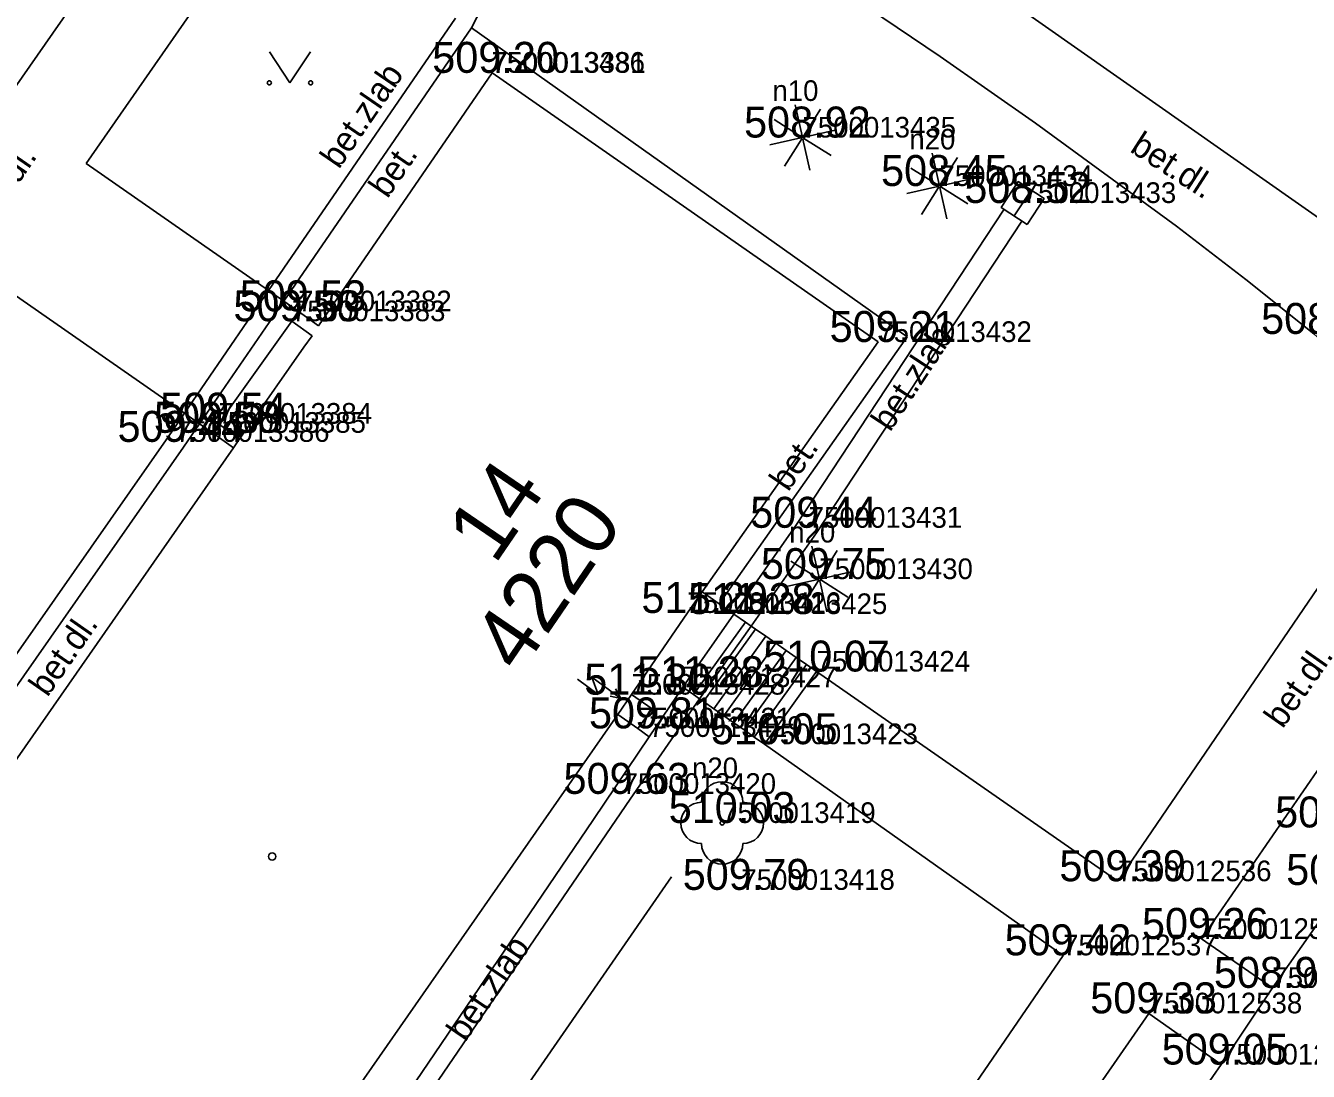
# Model space of a CAD drawing. Extents: x -669251 to -668549, y -1128351 to -1127698.
# Drawn here: x -668889.3 to -668858.22, y -1127834.53 to -1127809.2 of the extents above; entities that cross this region are included whole.
import ezdxf

# ---------------------------------------------------------------- set-up
doc = ezdxf.new("R2010")
doc.units = 0
for name, color, linetype in [('Vrstva 1', 7, 'Continuous'), ('Vrstva 10', 7, 'Continuous'), ('Vrstva 11', 7, 'Continuous'), ('Vrstva 14', 7, 'Continuous'), ('Vrstva 2', 7, 'Continuous'), ('Vrstva 22', 7, 'Continuous'), ('Vrstva 24', 7, 'Continuous'), ('Vrstva 27', 7, 'Continuous'), ('Vrstva 3', 7, 'Continuous'), ('Vrstva 36', 7, 'Continuous'), ('Vrstva 40', 7, 'Continuous'), ('Vrstva 43', 7, 'Continuous'), ('Vrstva 44', 7, 'Continuous'), ('Vrstva 47', 7, 'Continuous'), ('Vrstva 5', 7, 'Continuous'), ('Vrstva 58', 7, 'Continuous'), ('Vrstva 6', 7, 'Continuous')]:
    doc.layers.add(name, color=color, linetype=linetype)

msp = doc.modelspace()

# ---------------------------------------------------------------- linework, layer by layer
at = {"layer": 'Vrstva 1'}
for p, q in [((-668878.013, -1127810.343), (-668878.013, -1127810.343)), ((-668877.996, -1127810.346), (-668877.996, -1127810.346)), ((-668870.478, -1127811.913), (-668870.478, -1127811.913)), ((-668867.161, -1127813.087), (-668867.161, -1127813.087)), ((-668865.144, -1127813.498), (-668865.144, -1127813.498)), ((-668882.696, -1127816.122), (-668882.696, -1127816.122)), ((-668882.848, -1127816.362), (-668882.848, -1127816.362)), ((-668868.642, -1127816.865), (-668868.642, -1127816.865)), ((-668884.627, -1127818.844), (-668884.627, -1127818.844)), ((-668885.656, -1127819.284), (-668885.656, -1127819.284)), ((-668884.775, -1127819.064), (-668884.775, -1127819.064)), ((-668870.329, -1127821.365), (-668870.329, -1127821.365)), ((-668870.07, -1127822.608), (-668870.07, -1127822.608)), ((-668873.267, -1127823.428), (-668873.267, -1127823.428)), ((-668872.143, -1127823.455), (-668872.143, -1127823.455)), ((-668870.137, -1127824.847), (-668870.137, -1127824.847)), ((-668874.62, -1127825.406), (-668874.62, -1127825.406)), ((-668873.376, -1127825.226), (-668873.376, -1127825.226)), ((-668874.472, -1127826.224), (-668874.472, -1127826.224)), ((-668874.193, -1127826.431), (-668874.193, -1127826.431)), ((-668871.401, -1127826.607), (-668871.401, -1127826.607)), ((-668874.838, -1127827.81), (-668874.838, -1127827.81)), ((-668872.425, -1127828.515), (-668872.425, -1127828.515)), ((-668871.96, -1127830.135), (-668871.96, -1127830.135)), ((-668862.836, -1127829.926), (-668862.836, -1127829.926)), ((-668860.815, -1127831.323), (-668860.815, -1127831.323)), ((-668864.165, -1127831.721), (-668864.165, -1127831.721)), ((-668859.096, -1127832.509), (-668859.096, -1127832.509)), ((-668862.091, -1127833.126), (-668862.091, -1127833.126)), ((-668860.339, -1127834.366), (-668860.339, -1127834.366))]:
    msp.add_line(p, q, dxfattribs=at)
at = {"layer": 'Vrstva 10'}
for p, q in [((-668907.589, -1127779.058), (-668856.591, -1127814.83)), ((-668879.97, -1127801.247), (-668887.836, -1127812.543)), ((-668900.288, -1127826.082), (-668886.406, -1127806.172)), ((-668876.868, -1127806.118), (-668878.5, -1127809.256)), ((-668878.886, -1127809.024), (-668883.415, -1127815.621)), ((-668878.5, -1127809.256), (-668883.045, -1127815.878)), ((-668878.5, -1127809.256), (-668867.944, -1127816.742)), ((-668883.415, -1127815.621), (-668887.836, -1127812.543)), ((-668865.594, -1127813.65), (-668870.64, -1127821.307)), ((-668865.162, -1127813.935), (-668870.143, -1127821.491)), ((-668885.454, -1127818.591), (-668889.894, -1127815.499)), ((-668883.415, -1127815.621), (-668885.454, -1127818.591)), ((-668883.045, -1127815.878), (-668883.415, -1127815.621)), ((-668883.045, -1127815.878), (-668885.084, -1127818.848)), ((-668882.696, -1127816.122), (-668883.045, -1127815.878)), ((-668867.944, -1127816.742), (-668872.498, -1127823.205)), ((-668885.454, -1127818.591), (-668885.841, -1127819.156)), ((-668885.084, -1127818.848), (-668885.454, -1127818.591)), ((-668885.084, -1127818.848), (-668885.471, -1127819.412)), ((-668884.775, -1127819.064), (-668885.084, -1127818.848)), ((-668893.205, -1127829.685), (-668885.841, -1127819.156)), ((-668855.496, -1127819.148), (-668862.836, -1127829.926)), ((-668892.835, -1127829.943), (-668885.471, -1127819.412)), ((-668870.64, -1127821.307), (-668872.143, -1127823.455)), ((-668870.143, -1127821.491), (-668871.721, -1127823.748)), ((-668860.815, -1127831.323), (-668854.159, -1127821.653)), ((-668871.721, -1127823.748), (-668872.974, -1127825.506)), ((-668862.836, -1127829.926), (-668870.137, -1127824.847)), ((-668872.974, -1127825.506), (-668874.654, -1127827.939)), ((-668874.193, -1127826.431), (-668875.54, -1127828.434)), ((-668871.401, -1127826.607), (-668864.165, -1127831.721)), ((-668874.654, -1127827.939), (-668881.914, -1127838.571)), ((-668875.54, -1127828.434), (-668882.273, -1127838.332)), ((-668859.096, -1127832.509), (-668857.344, -1127830.016)), ((-668860.815, -1127831.323), (-668859.096, -1127832.509)), ((-668872.983, -1127844.597), (-668864.165, -1127831.721)), ((-668860.339, -1127834.366), (-668859.096, -1127832.509)), ((-668871.001, -1127845.97), (-668862.091, -1127833.126)), ((-668862.091, -1127833.126), (-668860.339, -1127834.366)), ((-668869.228, -1127847.16), (-668860.339, -1127834.366))]:
    msp.add_line(p, q, dxfattribs=at)
msp.add_lwpolyline([(-668879.97, -1127801.247), (-668874.443, -1127805.031), (-668870.265, -1127807.831), (-668867.147, -1127809.949), (-668864.831, -1127811.565), (-668861.415, -1127814.059), (-668859.741, -1127815.348), (-668858.095, -1127816.67), (-668857.422, -1127817.261), (-668856.456, -1127818.201), (-668855.496, -1127819.148)], dxfattribs=at)
at = {"layer": 'Vrstva 11'}
for p, q in [((-668872.907, -1127822.917), (-668872.498, -1127823.205)), ((-668872.498, -1127823.205), (-668872.143, -1127823.455)), ((-668872.143, -1127823.455), (-668873.376, -1127825.226)), ((-668872.143, -1127823.455), (-668871.863, -1127823.65)), ((-668871.863, -1127823.65), (-668873.122, -1127825.403)), ((-668871.616, -1127823.821), (-668872.876, -1127825.575)), ((-668871.616, -1127823.821), (-668871.37, -1127823.992)), ((-668871.37, -1127823.992), (-668872.63, -1127825.747)), ((-668871.123, -1127824.163), (-668872.385, -1127825.919)), ((-668871.37, -1127823.992), (-668871.123, -1127824.163)), ((-668871.123, -1127824.163), (-668870.877, -1127824.334)), ((-668870.877, -1127824.334), (-668872.139, -1127826.091)), ((-668870.63, -1127824.505), (-668871.893, -1127826.263)), ((-668870.877, -1127824.334), (-668870.63, -1127824.505)), ((-668870.63, -1127824.505), (-668870.384, -1127824.676)), ((-668870.384, -1127824.676), (-668871.647, -1127826.435)), ((-668870.137, -1127824.847), (-668871.401, -1127826.607)), ((-668870.384, -1127824.676), (-668870.137, -1127824.847)), ((-668873.376, -1127825.226), (-668874.193, -1127826.431)), ((-668873.376, -1127825.226), (-668873.122, -1127825.403)), ((-668873.122, -1127825.403), (-668872.974, -1127825.506)), ((-668872.974, -1127825.506), (-668872.876, -1127825.575)), ((-668872.876, -1127825.575), (-668872.63, -1127825.747)), ((-668872.63, -1127825.747), (-668872.385, -1127825.919)), ((-668874.955, -1127825.887), (-668874.472, -1127826.224)), ((-668872.385, -1127825.919), (-668872.139, -1127826.091)), ((-668872.139, -1127826.091), (-668871.893, -1127826.263)), ((-668874.193, -1127826.431), (-668874.472, -1127826.224)), ((-668871.893, -1127826.263), (-668871.647, -1127826.435)), ((-668871.647, -1127826.435), (-668871.401, -1127826.607))]:
    msp.add_line(p, q, dxfattribs=at)
msp.add_lwpolyline([(-668871.863, -1127823.65), (-668871.721, -1127823.748), (-668871.616, -1127823.821)], dxfattribs=at)
at = {"layer": 'Vrstva 14'}
msp.add_line((-668880.4, -1127839.579), (-668873.655, -1127829.816), dxfattribs=at)
at = {"layer": 'Vrstva 22'}
for p, q in [((-668870.486, -1127811.873), (-668870.658, -1127811.119)), ((-668870.512, -1127811.893), (-668871.168, -1127811.479)), ((-668870.044, -1127811.223), (-668870.458, -1127811.879)), ((-668870.438, -1127811.905), (-668869.684, -1127811.733)), ((-668871.272, -1127812.093), (-668870.518, -1127811.921)), ((-668870.498, -1127811.947), (-668870.912, -1127812.603)), ((-668870.47, -1127811.953), (-668870.298, -1127812.707)), ((-668869.788, -1127812.347), (-668870.444, -1127811.933)), ((-668867.169, -1127813.047), (-668867.341, -1127812.293)), ((-668866.727, -1127812.397), (-668867.141, -1127813.053)), ((-668867.195, -1127813.067), (-668867.851, -1127812.653)), ((-668867.121, -1127813.079), (-668866.367, -1127812.907)), ((-668867.955, -1127813.267), (-668867.201, -1127813.095)), ((-668867.181, -1127813.121), (-668867.595, -1127813.777)), ((-668867.153, -1127813.127), (-668866.981, -1127813.881)), ((-668866.471, -1127813.521), (-668867.127, -1127813.107)), ((-668870.078, -1127822.568), (-668870.25, -1127821.814)), ((-668869.636, -1127821.918), (-668870.05, -1127822.574)), ((-668870.104, -1127822.588), (-668870.76, -1127822.174)), ((-668870.864, -1127822.788), (-668870.11, -1127822.616)), ((-668870.09, -1127822.642), (-668870.504, -1127823.298)), ((-668870.062, -1127822.648), (-668869.89, -1127823.402)), ((-668869.38, -1127823.042), (-668870.036, -1127822.628)), ((-668870.03, -1127822.6), (-668869.276, -1127822.428))]:
    msp.add_line(p, q, dxfattribs=at)
for centre, radius in [((-668870.478, -1127811.913), 0.04), ((-668867.161, -1127813.087), 0.04), ((-668870.07, -1127822.608), 0.04), ((-668872.425, -1127828.515), 0.05)]:
    msp.add_circle(centre, radius, dxfattribs=at)
for centre, start, end in [((-668872.425, -1127828.015), 0, 180), ((-668872.925, -1127828.515), 90, 270), ((-668871.925, -1127828.515), 270, 90), ((-668872.425, -1127829.015), 180, 0)]:
    msp.add_arc(centre, 0.5, start, end, dxfattribs=at)
at = {"layer": 'Vrstva 24'}
for p, q in [((-668875.933, -1127825.032), (-668875.43, -1127825.405)), ((-668875.43, -1127825.405), (-668875.582, -1127824.981)), ((-668875.582, -1127824.981), (-668874.88, -1127825.502)), ((-668875.142, -1127825.445), (-668874.88, -1127825.502)), ((-668874.88, -1127825.502), (-668875.011, -1127825.268)), ((-668874.62, -1127825.406), (-668874.123, -1127825.754)), ((-668874.122, -1127825.753), (-668874.472, -1127826.224))]:
    msp.add_line(p, q, dxfattribs=at)
at = {"layer": 'Vrstva 27'}
msp.add_line((-668865.35, -1127813.811), (-668864.938, -1127813.185), dxfattribs=at)
msp.add_lwpolyline([(-668865.038, -1127814.017), (-668864.625, -1127813.391), (-668865.252, -1127812.978), (-668865.664, -1127813.604)], close=True, dxfattribs=at)
at = {"layer": 'Vrstva 36'}
for p, q in [((-668883.395, -1127809.838), (-668882.895, -1127810.588)), ((-668882.895, -1127810.588), (-668882.395, -1127809.838))]:
    msp.add_line(p, q, dxfattribs=at)
for centre in [(-668883.396, -1127810.588), (-668882.396, -1127810.588)]:
    msp.add_circle(centre, 0.05, dxfattribs=at)
at = {"layer": 'Vrstva 5'}
for p, q in [((-668882.208, -1127816.472), (-668877.996, -1127810.346)), ((-668877.996, -1127810.346), (-668868.642, -1127816.865)), ((-668882.696, -1127816.122), (-668882.848, -1127816.362)), ((-668882.208, -1127816.472), (-668882.696, -1127816.122)), ((-668882.848, -1127816.362), (-668884.627, -1127818.844)), ((-668882.36, -1127816.712), (-668882.848, -1127816.362)), ((-668882.36, -1127816.712), (-668882.556, -1127816.99)), ((-668868.642, -1127816.865), (-668872.907, -1127822.917)), ((-668884.627, -1127818.844), (-668884.775, -1127819.064)), ((-668884.115, -1127819.211), (-668884.627, -1127818.844)), ((-668884.115, -1127819.211), (-668883.925, -1127818.941)), ((-668884.266, -1127819.429), (-668884.775, -1127819.064)), ((-668884.266, -1127819.429), (-668884.115, -1127819.211)), ((-668892.499, -1127831.244), (-668884.266, -1127819.429)), ((-668872.907, -1127822.917), (-668873.267, -1127823.428)), ((-668874.955, -1127825.887), (-668874.62, -1127825.406)), ((-668883.188, -1127837.699), (-668874.955, -1127825.887))]:
    msp.add_line(p, q, dxfattribs=at)
at = {"layer": 'Vrstva 58'}
msp.add_circle((-668883.326, -1127829.326), 0.0875, dxfattribs=at)
at = {"layer": 'Vrstva 6'}
for p, q in [((-668882.556, -1127816.99), (-668883.925, -1127818.941)), ((-668874.62, -1127825.406), (-668873.267, -1127823.428))]:
    msp.add_line(p, q, dxfattribs=at)

# ---------------------------------------------------------------- texts
at = {"layer": 'Vrstva 2'}
for s, p in [('7500013436', (-668878.013, -1127810.343)), ('7500013381', (-668877.996, -1127810.346)), ('7500013435', (-668870.478, -1127811.913)), ('7500013434', (-668867.161, -1127813.087)), ('7500013433', (-668865.144, -1127813.498)), ('7500013383', (-668882.848, -1127816.362)), ('7500013382', (-668882.696, -1127816.122)), ('7500013432', (-668868.642, -1127816.865)), ('7500013384', (-668884.627, -1127818.844)), ('7500013385', (-668884.775, -1127819.064)), ('7500013386', (-668885.656, -1127819.284)), ('7500013431', (-668870.329, -1127821.365)), ('7500013430', (-668870.07, -1127822.608)), ('7500013426', (-668873.267, -1127823.428)), ('7500013425', (-668872.143, -1127823.455)), ('7500013424', (-668870.137, -1127824.847)), ('7500013427', (-668873.376, -1127825.226)), ('7500013428', (-668874.62, -1127825.406)), ('7500013421', (-668874.472, -1127826.224)), ('7500013429', (-668874.193, -1127826.431)), ('7500013423', (-668871.401, -1127826.607)), ('7500013420', (-668874.838, -1127827.81)), ('7500013419', (-668872.425, -1127828.515)), ('7500012536', (-668862.836, -1127829.926)), ('7500013418', (-668871.96, -1127830.135)), ('7500012539', (-668860.815, -1127831.323)), ('7500012537', (-668864.165, -1127831.721)), ('7500012540', (-668859.096, -1127832.509)), ('7500012538', (-668862.091, -1127833.126)), ('7500012541', (-668860.339, -1127834.366))]:
    msp.add_text(s, height=0.5, dxfattribs=at).set_placement(p)
at = {"layer": 'Vrstva 3'}
for s, p in [('509.20 ', (-668879.449, -1127810.346)), ('508.92 ', (-668871.895, -1127811.913)), ('508.45 ', (-668868.576, -1127813.087)), ('508.52 ', (-668866.559, -1127813.498)), ('509.53 ', (-668884.113, -1127816.122)), ('509.53 ', (-668884.265, -1127816.362)), ('509.21 ', (-668869.822, -1127816.865)), ('508.14 ', (-668859.369, -1127816.67)), ('509.58 ', (-668886.192, -1127819.064)), ('509.54 ', (-668886.044, -1127818.844)), ('509.44 ', (-668887.073, -1127819.284)), ('509.44 ', (-668871.746, -1127821.365)), ('509.75 ', (-668871.487, -1127822.608)), ('511.29 ', (-668874.381, -1127823.428)), ('511.28 ', (-668873.253, -1127823.455)), ('510.07 ', (-668871.432, -1127824.847)), ('511.28 ', (-668874.486, -1127825.226)), ('511.30 ', (-668875.766, -1127825.406)), ('509.81 ', (-668875.652, -1127826.224)), ('510.05 ', (-668872.696, -1127826.607)), ('509.63 ', (-668876.269, -1127827.81)), ('510.03 ', (-668873.72, -1127828.515)), ('508.94 ', (-668859.029, -1127828.623)), ('509.39 ', (-668864.256, -1127829.926)), ('509.79 ', (-668873.38, -1127830.135)), ('508.92 ', (-668858.761, -1127830.016)), ('509.26 ', (-668862.255, -1127831.323)), ('509.42 ', (-668865.582, -1127831.721)), ('508.98 ', (-668860.513, -1127832.509)), ('509.33 ', (-668863.508, -1127833.126)), ('509.05 ', (-668861.777, -1127834.366))]:
    msp.add_text(s, height=0.75, dxfattribs=at).set_placement(p)
at = {"layer": 'Vrstva 40'}
for s, rotation, p in [('bet.zlab', 55.5337, (-668881.71, -1127812.698)), ('bet.dl.', 327.238, (-668862.574, -1127812.24)), ('bet.dl.', 55.4547, (-668890.242, -1127814.166)), ('bet.', 55.485, (-668880.534, -1127813.411)), ('bet.zlab', 56.6118, (-668868.356, -1127819.063)), ('bet.', 55.485, (-668870.826, -1127820.512)), ('bet.dl.', 55.1291, (-668888.77, -1127825.485)), ('bet.dl.', 55.0494, (-668858.847, -1127826.25)), ('bet.zlab', 55.6689, (-668878.647, -1127833.837))]:
    msp.add_text(s, height=0.6, rotation=rotation, dxfattribs=at).set_placement(p)
at = {"layer": 'Vrstva 43'}
msp.add_text('4220', height=1.5, rotation=55.6269, dxfattribs=at).set_placement((-668877.321, -1127824.926))
at = {"layer": 'Vrstva 44'}
msp.add_text('14', height=1.5, rotation=55.6269, dxfattribs=at).set_placement((-668877.933, -1127822.28))
at = {"layer": 'Vrstva 47'}
for s, height, p in [('n10', 0.5, (-668871.208, -1127811.027)), ('n20', 0.5, (-668867.891, -1127812.201)), ('n20', 0.5, (-668870.8, -1127821.722)), ('n20', 0.499, (-668873.154, -1127827.429))]:
    msp.add_text(s, height=height, dxfattribs=at).set_placement(p)

doc.saveas('drawing.dxf')
